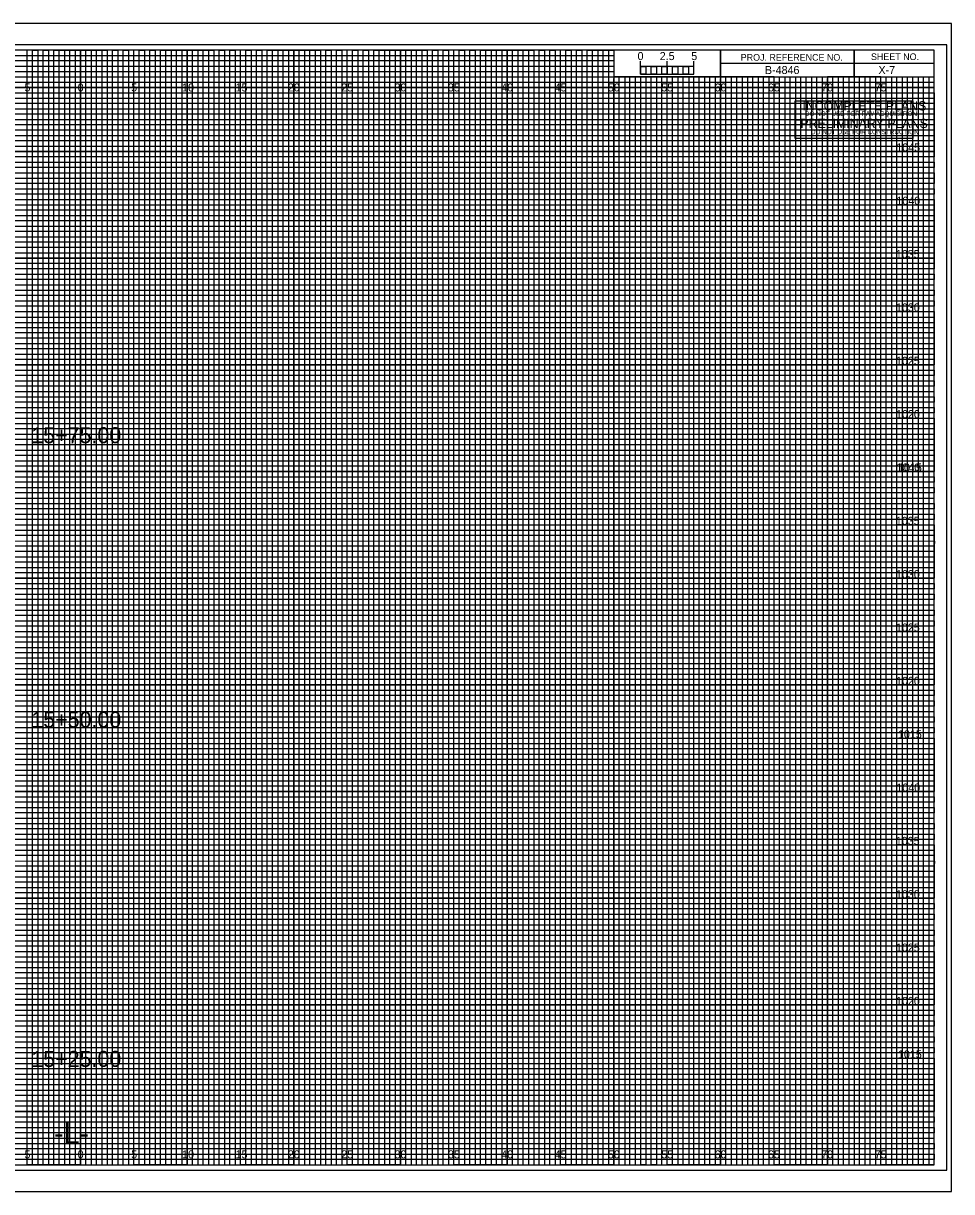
# Model space of a CAD drawing. Extents: x -7 to 162, y -2 to 987.
# Drawn here: x 74.6 to 161.7, y 657.5 to 767 of the extents above; entities that cross this region are included whole.
import ezdxf

# ---------------------------------------------------------------- set-up
doc = ezdxf.new("R2010")
doc.units = 0
for name, color, linetype in [('Default', 7, 'Continuous'), ('Exist Cross Section Cell', 7, 'Continuous'), ('Exist XS Center Line Elevation Label', 7, 'Continuous'), ('Exist XS Ground Line', 7, 'Continuous'), ('Prop CMT Concrete Structures', 7, 'Continuous'), ('Prop CMT DNC', 7, 'Continuous'), ('Prop CMT Guardrail Graphics', 7, 'Continuous'), ('Prop CMT Guardrail Widen Shoulder', 7, 'Continuous'), ('Prop CMT Pvmt Course 1', 7, 'Continuous'), ('Prop CMT Pvmt Surface', 7, 'Continuous'), ('Prop CMT Pvmt Surface Shoulder', 7, 'Continuous'), ('Prop CMT Shld Paved Course 1', 7, 'Continuous'), ('Prop CMT Shoulder Point', 7, 'Continuous'), ('Prop CMT Slope Grass', 7, 'Continuous'), ('Prop CMT Subgrade Earthwork', 7, 'Continuous'), ('Prop XS SE Text', 7, 'Continuous'), ('Prop XS Side Slope Text', 7, 'Continuous'), ('Typical Text Label CELL', 7, 'Continuous')]:
    doc.layers.add(name, color=color, linetype=linetype)

msp = doc.modelspace()

# ---------------------------------------------------------------- linework, layer by layer
at = {"layer": 'Default'}
for points in [[(146.99, 757.97), (146.99, 759.73), (158.01, 759.73), (158.01, 757.97)], [(146.99, 756.2), (146.99, 757.97), (158.01, 757.97), (158.01, 756.2)]]:
    msp.add_lwpolyline(points, close=True, dxfattribs=at)
at = {"layer": 'Exist XS Center Line Elevation Label'}
for points in [[(72.5, 660), (77.5, 660), (77.5, 764.5), (82.5, 764.5), (82.5, 660), (87.5, 660), (87.5, 764.5), (92.5, 764.5), (92.5, 660), (97.5, 660), (97.5, 764.5), (102.5, 764.5), (102.5, 660), (107.5, 660), (107.5, 764.5), (112.5, 764.5), (112.5, 660), (117.5, 660), (117.5, 764.5), (122.5, 764.5), (122.5, 660), (127.5, 660), (127.5, 764.5), (129.97, 764.5), (130, 764.5), (130, 762), (132.5, 762), (132.5, 660), (137.5, 660), (137.5, 762), (142.5, 762), (142.5, 660), (147.5, 660), (147.5, 762), (152.5, 762), (152.5, 660), (157.5, 660), (157.5, 762)], [(0, 762), (137.5, 762)], [(0, 752.5), (160, 752.5), (160, 757.5), (0, 757.5)], [(0, 742.5), (160, 742.5), (160, 747.5), (0, 747.5)], [(0, 732.5), (160, 732.5), (160, 737.5), (0, 737.5)], [(0, 722.5), (160, 722.5), (160, 727.5), (0, 727.5)], [(0, 712.5), (160, 712.5), (160, 717.5), (0, 717.5)], [(0, 702.5), (160, 702.5), (160, 707.5), (0, 707.5)], [(0, 692.5), (160, 692.5), (160, 697.5), (0, 697.5)], [(0, 682.5), (160, 682.5), (160, 687.5), (0, 687.5)], [(0, 672.5), (160, 672.5), (160, 677.5), (0, 677.5)], [(0, 662.5), (160, 662.5), (160, 667.5), (0, 667.5)]]:
    msp.add_lwpolyline(points, dxfattribs=at)
at = {"layer": 'Exist XS Ground Line'}
for p, q in [((75, 764.5), (70, 764.5)), ((75, 660), (75, 764.5)), ((85, 764.5), (80, 764.5)), ((80, 764.5), (80, 660)), ((85, 660), (85, 764.5)), ((95, 764.5), (90, 764.5)), ((90, 764.5), (90, 660)), ((95, 660), (95, 764.5)), ((105, 764.5), (100, 764.5)), ((100, 764.5), (100, 660)), ((105, 660), (105, 764.5)), ((115, 764.5), (110, 764.5)), ((110, 764.5), (110, 660)), ((115, 660), (115, 764.5)), ((125, 764.5), (120, 764.5)), ((120, 764.5), (120, 660)), ((125, 660), (125, 764.5)), ((130, 764.5), (130, 660)), ((135, 660), (135, 762)), ((145, 762), (140, 762)), ((140, 762), (140, 660)), ((145, 660), (145, 762)), ((155, 762), (150, 762)), ((150, 762), (150, 660)), ((155, 660), (155, 762)), ((80, 660), (75, 660)), ((90, 660), (85, 660)), ((100, 660), (95, 660)), ((110, 660), (105, 660)), ((120, 660), (115, 660)), ((130, 660), (125, 660)), ((140, 660), (135, 660)), ((150, 660), (145, 660)), ((160, 660), (155, 660)), ((160, 660), (160, 660))]:
    msp.add_line(p, q, dxfattribs=at)
for points in [[(0, 760), (160, 760), (160, 755), (0, 755)], [(0, 750), (160, 750), (160, 745), (0, 745)], [(0, 740), (160, 740), (160, 735), (0, 735)], [(0, 730), (160, 730), (160, 725), (0, 725)], [(0, 720), (160, 720), (160, 715), (0, 715)], [(0, 710), (160, 710), (160, 705), (0, 705)], [(0, 700), (160, 700), (160, 695), (0, 695)], [(0, 690), (160, 690), (160, 685), (0, 685)], [(0, 680), (160, 680), (160, 675), (0, 675)], [(0, 670), (160, 670), (160, 665), (0, 665)]]:
    msp.add_lwpolyline(points, dxfattribs=at)
at = {"layer": 'Prop CMT Concrete Structures'}
for p, q in [((75, 660), (75, 764.5)), ((80, 660), (80, 764.5)), ((85, 660), (85, 764.5)), ((90, 660), (90, 764.5)), ((95, 660), (95, 764.5)), ((100, 660), (100, 764.5)), ((105, 660), (105, 764.5)), ((110, 660), (110, 764.5)), ((115, 660), (115, 764.5)), ((120, 660), (120, 764.5)), ((125, 660), (125, 764.5)), ((130, 660), (130, 761.84)), ((135, 660), (135, 761.84)), ((140, 660), (140, 761.84)), ((145, 660), (145, 761.84)), ((150, 660), (150, 761.84)), ((155, 660), (155, 761.84)), ((0, 760), (160, 760)), ((0, 755), (160, 755)), ((0, 750), (160, 750)), ((0, 745), (160, 745)), ((0, 740), (160, 740)), ((0, 735), (160, 735)), ((0, 730), (160, 730)), ((0, 725), (160, 725)), ((0, 720), (160, 720)), ((0, 715), (160, 715)), ((0, 710), (160, 710)), ((0, 705), (160, 705)), ((0, 700), (160, 700)), ((0, 695), (160, 695)), ((0, 690), (160, 690)), ((0, 685), (160, 685)), ((0, 680), (160, 680)), ((0, 675), (160, 675)), ((0, 670), (160, 670)), ((0, 665), (160, 665))]:
    msp.add_line(p, q, dxfattribs=at)
at = {"layer": 'Prop CMT Guardrail Widen Shoulder'}
for p, q in [((161.65, 767), (-6.7, 767)), ((-6.7, 657.5), (161.65, 657.5))]:
    msp.add_line(p, q, dxfattribs=at)
at = {"layer": 'Prop CMT Pvmt Course 1'}
msp.add_lwpolyline([(-6.7, 657.5), (161.65, 657.5), (161.65, 767), (-6.7, 767)], close=True, dxfattribs=at)
at = {"layer": 'Prop CMT Pvmt Surface'}
for p, q in [((133.5, 762), (133, 762)), ((133, 762), (133, 660)), ((133.5, 660), (133.5, 762)), ((134.5, 762), (134, 762)), ((134, 762), (134, 660)), ((134.5, 660), (134.5, 762)), ((133, 660), (132.5, 660)), ((134, 660), (133.5, 660))]:
    msp.add_line(p, q, dxfattribs=at)
for points in [[(75, 660), (75.5, 660), (75.5, 764.5), (76, 764.5), (76, 660)], [(76, 660), (76.5, 660), (76.5, 764.5), (77, 764.5), (77, 660)], [(77.5, 660), (78, 660), (78, 764.5), (78.5, 764.5), (78.5, 660)], [(78.5, 660), (79, 660), (79, 764.5), (79.5, 764.5), (79.5, 660)], [(80, 660), (80.5, 660), (80.5, 764.5), (81, 764.5), (81, 660)], [(81, 660), (81.5, 660), (81.5, 764.5), (82, 764.5), (82, 660)], [(82.5, 660), (83, 660), (83, 764.5), (83.5, 764.5), (83.5, 660)], [(83.5, 660), (84, 660), (84, 764.5), (84.5, 764.5), (84.5, 660)], [(85, 660), (85.5, 660), (85.5, 764.5), (86, 764.5), (86, 660)], [(86, 660), (86.5, 660), (86.5, 764.5), (87, 764.5), (87, 660)], [(87.5, 660), (88, 660), (88, 764.5), (88.5, 764.5), (88.5, 660)], [(88.5, 660), (89, 660), (89, 764.5), (89.5, 764.5), (89.5, 660)], [(90, 660), (90.5, 660), (90.5, 764.5), (91, 764.5), (91, 660)], [(91, 660), (91.5, 660), (91.5, 764.5), (92, 764.5), (92, 660)], [(92.5, 660), (93, 660), (93, 764.5), (93.5, 764.5), (93.5, 660)], [(93.5, 660), (94, 660), (94, 764.5), (94.5, 764.5), (94.5, 660)], [(95, 660), (95.5, 660), (95.5, 764.5), (96, 764.5), (96, 660)], [(96, 660), (96.5, 660), (96.5, 764.5), (97, 764.5), (97, 660)], [(97.5, 660), (98, 660), (98, 764.5), (98.5, 764.5), (98.5, 660)], [(98.5, 660), (99, 660), (99, 764.5), (99.5, 764.5), (99.5, 660)], [(100, 660), (100.5, 660), (100.5, 764.5), (101, 764.5), (101, 660)], [(101, 660), (101.5, 660), (101.5, 764.5), (102, 764.5), (102, 660)], [(102.5, 660), (103, 660), (103, 764.5), (103.5, 764.5), (103.5, 660)], [(103.5, 660), (104, 660), (104, 764.5), (104.5, 764.5), (104.5, 660)], [(105, 660), (105.5, 660), (105.5, 764.5), (106, 764.5), (106, 660)], [(106, 660), (106.5, 660), (106.5, 764.5), (107, 764.5), (107, 660)], [(107.5, 660), (108, 660), (108, 764.5), (108.5, 764.5), (108.5, 660)], [(108.5, 660), (109, 660), (109, 764.5), (109.5, 764.5), (109.5, 660)], [(110, 660), (110.5, 660), (110.5, 764.5), (111, 764.5), (111, 660)], [(111, 660), (111.5, 660), (111.5, 764.5), (112, 764.5), (112, 660)], [(112.5, 660), (113, 660), (113, 764.5), (113.5, 764.5), (113.5, 660)], [(113.5, 660), (114, 660), (114, 764.5), (114.5, 764.5), (114.5, 660)], [(115, 660), (115.5, 660), (115.5, 764.5), (116, 764.5), (116, 660)], [(116, 660), (116.5, 660), (116.5, 764.5), (117, 764.5), (117, 660)], [(117.5, 660), (118, 660), (118, 764.5), (118.5, 764.5), (118.5, 660)], [(118.5, 660), (119, 660), (119, 764.5), (119.5, 764.5), (119.5, 660)], [(120, 660), (120.5, 660), (120.5, 764.5), (121, 764.5), (121, 660)], [(121, 660), (121.5, 660), (121.5, 764.5), (122, 764.5), (122, 660)], [(122.5, 660), (123, 660), (123, 764.5), (123.5, 764.5), (123.5, 660)], [(123.5, 660), (124, 660), (124, 764.5), (124.5, 764.5), (124.5, 660)], [(125, 660), (125.5, 660), (125.5, 764.5), (126, 764.5), (126, 660)], [(126, 660), (126.5, 660), (126.5, 764.5), (127, 764.5), (127, 660)], [(127.5, 660), (128, 660), (128, 764.5), (128.5, 764.5), (128.5, 660)], [(128.5, 660), (129, 660), (129, 764.5), (129.5, 764.5), (129.5, 660)], [(130, 660), (130.5, 660), (130.5, 762), (131.01, 762), (131.01, 660)], [(131, 660), (131.5, 660), (131.5, 762), (132, 762), (132, 660)], [(135, 660), (135.49, 660), (135.49, 762), (136, 762), (136, 660)], [(136, 660), (136.5, 660), (136.5, 762), (137.03, 762), (137.03, 660)], [(137.5, 660), (138, 660), (138, 762), (138.5, 762), (138.5, 660)], [(138.5, 660), (139, 660), (139, 762), (139.5, 762), (139.5, 660)], [(140, 660), (140.5, 660), (140.5, 762), (141, 762), (141, 660)], [(141, 660), (141.5, 660), (141.5, 762), (142, 762), (142, 660)], [(142.5, 660), (143, 660), (143, 762), (143.5, 762), (143.5, 660)], [(143.5, 660), (144, 660), (144, 762), (144.5, 762), (144.5, 660)], [(145, 660), (145.5, 660), (145.5, 762), (146, 762), (146, 660)], [(146, 660), (146.5, 660), (146.5, 762), (147, 762), (147, 660)], [(147.5, 660), (148, 660), (148, 762), (148.5, 762), (148.5, 660)], [(148.5, 660), (149, 660), (149, 762), (149.5, 762), (149.5, 660)], [(150, 660), (150.5, 660), (150.5, 762), (151, 762), (151, 660)], [(151, 660), (151.5, 660), (151.5, 762), (152, 762), (152, 660)], [(152.5, 660), (153, 660), (153, 762), (153.5, 762), (153.5, 660)], [(153.5, 660), (154, 660), (154, 762), (154.5, 762), (154.5, 660)], [(155, 660), (155.5, 660), (155.5, 762), (156, 762), (156, 660)], [(156, 660), (156.5, 660), (156.5, 762), (157, 762), (157, 660)], [(157.5, 660), (158, 660), (158, 762), (158.5, 762), (158.5, 660)], [(158.5, 660), (159, 660), (159, 762), (159.5, 762), (159.5, 660)]]:
    msp.add_lwpolyline(points, dxfattribs=at)
at = {"layer": 'Prop CMT Pvmt Surface Shoulder'}
for p, q in [((132.5, 762.25), (132.5, 763.45)), ((132.5, 762.95), (132.5, 763.45)), ((135, 762.25), (135, 763.45)), ((137.5, 762.25), (137.5, 763.45)), ((137.5, 762.95), (137.5, 763.45))]:
    msp.add_line(p, q, dxfattribs=at)
for points in [[(137.5, 762.95), (132.5, 762.95), (132.5, 762.25), (137.5, 762.25)], [(132.5, 762.95), (133, 762.95), (133, 762.25), (132.5, 762.25)], [(133.5, 762.95), (134, 762.95), (134, 762.25), (133.5, 762.25)], [(134.5, 762.95), (135, 762.95), (135, 762.25), (134.5, 762.25)], [(135.5, 762.95), (136, 762.95), (136, 762.25), (135.5, 762.25)], [(136.5, 762.95), (137, 762.95), (137, 762.25), (136.5, 762.25)]]:
    msp.add_lwpolyline(points, close=True, dxfattribs=at)
at = {"layer": 'Prop CMT Shld Paved Course 1'}
for p, q in [((0, 764), (130, 764)), ((130, 763.49), (0, 763.49)), ((130, 764), (130, 763.49)), ((0, 763), (130, 763)), ((130, 762.45), (0, 762.45)), ((130, 763), (130, 762.45)), ((0, 761.5), (160, 761.5))]:
    msp.add_line(p, q, dxfattribs=at)
for points in [[(0, 761), (135, 761), (160, 761), (160, 761), (0, 761)], [(0, 760.5), (160, 760.5), (160, 759.5), (0, 759.5)], [(0, 759), (160, 759), (160, 758.5), (0, 758.49)], [(0, 758), (160, 758), (160, 757), (0, 757)], [(0, 756.5), (160, 756.5), (160, 756), (0, 756)], [(0, 755.5), (160, 755.5), (160, 754.5), (0, 754.5)], [(0, 754), (160, 754), (160, 753.5), (0, 753.5)], [(0, 753), (160, 753), (160, 752), (0, 752)], [(0, 751.5), (160, 751.5), (160, 751), (0, 751)], [(0, 750.5), (160, 750.5), (160, 749.5), (0, 749.5)], [(0, 749), (160, 749), (160, 748.5), (0, 748.5)], [(0, 748), (160, 748), (160, 746.98), (160, 746.5), (160, 746), (0, 746)], [(0, 747), (160, 747), (160, 746.5), (0, 746.5)], [(0, 745.5), (160, 745.5), (160, 744.5), (0, 744.51)], [(0, 744.51), (160, 744.5), (160, 744), (0, 744)], [(0, 743.5), (160, 743.5), (160, 743), (0, 743)], [(0, 742), (160, 742), (160, 741.5), (0, 741.5)], [(0, 741), (160, 741), (160, 740.5), (0, 740.5)], [(-0.04, 739.45), (160, 739.45), (160, 738.94), (-0.04, 738.94)], [(0, 738.5), (160, 738.5), (160, 738), (0, 738)], [(0, 737), (160, 737), (160, 736.5), (0, 736.5)], [(0, 736), (160, 736), (160, 735.5), (0, 735.5)], [(0, 734.5), (160, 734.5), (160, 734), (0, 734)], [(0, 733.5), (160, 733.5), (160, 733), (0, 733)], [(0, 732), (160, 732), (160, 731.5), (0, 731.5)], [(0, 731), (160, 731), (160, 730.5), (0, 730.5)], [(0, 729.5), (160, 729.5), (160, 728.99), (0, 729)], [(0, 728.5), (160, 728.5), (160, 728), (0, 728)], [(0, 727), (160, 727), (160, 726.5), (0, 726.5)], [(0, 726), (160, 726), (160, 725.5), (0, 725.5)], [(0, 724.5), (160, 724.5), (160, 724), (0, 724)], [(0, 723.5), (160, 723.5), (160, 723), (0, 723)], [(0, 722), (160, 722), (160, 721.5), (0, 721.5)], [(0, 721), (160, 721), (160, 720.5), (0, 720.5)], [(0, 719.5), (160, 719.5), (160, 719), (0, 719)], [(0, 718.5), (160.03, 718.46), (160, 718), (0, 718)], [(0, 717), (160, 717), (160, 716.5), (0, 716.5)], [(0, 716), (160, 716), (160, 715.5), (0, 715.5)], [(0, 714.5), (160, 714.5), (160, 714), (0, 714)], [(0, 713.5), (160, 713.5), (160, 713), (0, 713)], [(0, 712), (160, 712), (160, 711.5), (0, 711.5)], [(0, 711), (160, 711), (160, 710.5), (0, 710.5)], [(0, 709.5), (160, 709.5), (160, 709), (0, 709)], [(0, 708.5), (160, 708.5), (160, 708), (0, 708)], [(0, 707), (160, 707), (160, 706.5), (0, 706.5)], [(0, 706), (160, 706), (160, 705.5), (0, 705.5)], [(0, 704.5), (160, 704.5), (160, 704), (0, 704)], [(0, 703.5), (160, 703.5), (160, 703), (0, 703)], [(0, 702), (160, 702), (160, 701.5), (0, 701.5)], [(0, 701), (160, 701), (160, 700.5), (0, 700.5)], [(0, 699.5), (160, 699.5), (160, 698.99), (0, 699)], [(0, 698.5), (160, 698.5), (160, 698), (0, 698)], [(0, 697), (160, 697), (160, 696.5), (0, 696.5)], [(0, 696), (160, 696), (160, 695.5), (0, 695.5)], [(0, 694.5), (160, 694.5), (160, 694), (0, 694)], [(0, 693.5), (160, 693.5), (160, 693), (0, 693)], [(0, 692), (160, 692), (160, 691.5), (0, 691.5)], [(0, 691), (160, 691), (160, 690.5), (0, 690.5)], [(0, 689.5), (160, 689.5), (160, 689), (0, 689)], [(0, 688.5), (160.03, 688.46), (160, 688), (0, 688)], [(0, 687), (160, 687), (160, 686.5), (0, 686.5)], [(0, 686), (160, 686), (160, 685.5), (0, 685.5)], [(0, 684.5), (160, 684.5), (160, 684), (0, 684)], [(0, 683.5), (160, 683.5), (160, 683), (0, 683)], [(0, 682), (160, 682), (160, 681.5), (0, 681.5)], [(0, 681), (160, 681), (160, 680.5), (0, 680.5)], [(0, 679.5), (160, 679.5), (160, 679), (0, 679)], [(0, 678.5), (160, 678.5), (160, 678), (0, 678)], [(0, 677), (160, 677), (160, 676.5), (0, 676.5)], [(0, 676), (160, 676), (160, 675.5), (0, 675.5)], [(0, 674.5), (160, 674.5), (160, 674), (0, 674)], [(0, 673.5), (160, 673.5), (160, 673), (0, 673)], [(0, 672), (160, 672), (160, 671.5), (0, 671.5)], [(0, 671), (160, 671), (160, 670.5), (0, 670.5)], [(0, 669.5), (160, 669.5), (160, 669), (0, 669)], [(0, 668.5), (160, 668.5), (160, 668), (0, 668)], [(0, 667), (160, 667), (160, 666.5), (0, 666.5)], [(0, 666), (160, 666), (160, 665.5), (0, 665.5)], [(0, 664.5), (160, 664.5), (160, 664), (0, 664)], [(0, 663.5), (160, 663.5), (160, 663), (0, 663)], [(0, 662), (160, 662), (160, 661.5), (0, 661.5)], [(0, 661), (160, 661), (160, 660.5), (0, 660.5)]]:
    msp.add_lwpolyline(points, dxfattribs=at)
at = {"layer": 'Prop CMT Slope Grass'}
msp.add_lwpolyline([(-5.4, 659.5), (161.2, 659.5), (161.2, 765), (-5.4, 765)], close=True, dxfattribs=at)
at = {"layer": 'Prop CMT Subgrade Earthwork'}
for p, q in [((152.5, 764.5), (152.5, 762)), ((152.5, 762), (152.5, 764.5)), ((160, 763.25), (140, 763.25)), ((140, 763.25), (140, 762)), ((140, 762), (160, 762))]:
    msp.add_line(p, q, dxfattribs=at)
for points in [[(160, 764.5), (0, 764.5), (0, 660), (160, 660)], [(140, 764.5), (130, 764.5), (130, 762.01), (140, 762.01)], [(160, 764.5), (140, 764.5), (140, 762), (160, 762)]]:
    msp.add_lwpolyline(points, close=True, dxfattribs=at)

# ---------------------------------------------------------------- texts
at = {"layer": 'Default'}
for s, height, p in [('INCOMPLETE PLANS', 0.864, (147.66, 758.84)), ('PRELIMINARY PLANS', 0.864, (147.47, 757.19)), ('DO NOT USE FOR R/W ACQUISITION', 0.432, (147.9, 758.32)), ('DO NOT USE FOR CONSTRUCTION', 0.432, (148.46, 756.61))]:
    msp.add_text(s, height=height, dxfattribs=at).set_placement(p)
at = {"layer": 'Exist Cross Section Cell'}
for s, p in [('5', (74.74, 760.62)), ('0', (79.73, 760.62)), ('0', (79.73, 760.62)), ('5', (84.74, 760.62)), ('10', (89.52, 760.62)), ('15', (94.53, 760.62)), ('20', (99.43, 760.62)), ('25', (104.44, 760.62)), ('30', (109.43, 760.62)), ('35', (114.44, 760.62)), ('40', (119.43, 760.62)), ('45', (124.44, 760.62)), ('50', (129.43, 760.62)), ('55', (134.44, 760.62)), ('60', (139.43, 760.62)), ('65', (144.44, 760.62)), ('70', (149.43, 760.62)), ('75', (154.44, 760.62)), ('0', (79.73, 660.62)), ('0', (79.73, 660.62)), ('10', (89.52, 660.62)), ('20', (99.43, 660.62)), ('25', (104.44, 660.62)), ('30', (109.43, 660.62)), ('35', (114.44, 660.62)), ('40', (119.43, 660.62)), ('50', (129.43, 660.62)), ('60', (139.43, 660.62)), ('65', (144.44, 660.62)), ('70', (149.43, 660.62)), ('5', (74.74, 660.62)), ('5', (84.74, 660.62)), ('15', (94.53, 660.62)), ('45', (124.44, 660.62)), ('55', (134.44, 660.62)), ('75', (154.44, 660.62))]:
    msp.add_text(s, height=0.75, dxfattribs=at).set_placement(p)
at = {"layer": 'Prop CMT DNC'}
msp.add_text('-L-', height=2, dxfattribs=at).set_placement((77.53, 662))
at = {"layer": 'Prop CMT Guardrail Graphics'}
msp.add_text('B-4846', height=0.75, dxfattribs=at).set_placement((144.15, 762.25))
at = {"layer": 'Prop CMT Pvmt Surface Shoulder'}
msp.add_text('0', height=0.75, dxfattribs=at).set_placement((132.21, 763.56))
at = {"layer": 'Prop CMT Shoulder Point'}
for s, p in [('2.5', (134.29, 763.56)), ('5', (137.24, 763.56))]:
    msp.add_text(s, height=0.75, dxfattribs=at).set_placement(p)
at = {"layer": 'Prop CMT Subgrade Earthwork'}
for s, p in [('PROJ. REFERENCE NO.', (141.88, 763.5)), ('SHEET NO.', (154.09, 763.56))]:
    msp.add_text(s, height=0.625, dxfattribs=at).set_placement(p)
at = {"layer": 'Prop XS SE Text'}
msp.add_text('X-7', height=0.75, dxfattribs=at).set_placement((154.79, 762.25))
at = {"layer": 'Prop XS Side Slope Text'}
for s, p in [('15+75.00', (75.39, 727.65)), ('15+50.00', (75.39, 700.99)), ('15+25.00', (75.39, 669.19))]:
    msp.add_text(s, height=1.5, dxfattribs=at).set_placement(p)
at = {"layer": 'Typical Text Label CELL'}
for s, p in [('1045', (156.46, 755)), ('1040', (156.47, 750)), ('1035', (156.42, 745)), ('1030', (156.43, 740)), ('1025', (156.43, 735)), ('1020', (156.44, 730)), ('1040', (156.47, 725)), ('1015', (156.62, 725)), ('1035', (156.42, 720)), ('1030', (156.43, 715)), ('1025', (156.43, 710)), ('1020', (156.44, 705)), ('1015', (156.62, 700)), ('1040', (156.47, 695)), ('1035', (156.42, 690)), ('1030', (156.43, 685)), ('1025', (156.43, 680)), ('1020', (156.44, 675)), ('1015', (156.62, 670))]:
    msp.add_text(s, height=0.75, dxfattribs=at).set_placement(p)

doc.saveas('drawing.dxf')
